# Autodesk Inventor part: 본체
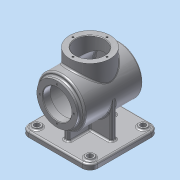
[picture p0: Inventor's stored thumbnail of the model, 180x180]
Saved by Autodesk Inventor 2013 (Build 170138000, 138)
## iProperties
Created: 2015-07
Part Number: 본체
Material: 알루미늄 6061
Document SubType Name: Modeling
Designer: Administrator
Density: 2.71 g/cm^3
Mass: 1277.74 g
Surface Area: 1267.61 cm^2
Volume: 471.49 cm^3
Author: Administrator
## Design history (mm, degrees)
sketch "스케치1"
  geometry: C1 r 45 at (0, 0); 1 further point
  constraints: 1 centre point, 1 coincident
  dimensions: "d0" = 90 diameter of C1
extrude "돌출1" new body sketch "스케치1" stored distance "d1" = 110; taper "d2" = 0 deg
sketch "스케치2"
  geometry: C1 r 45 at (0, 0) reference; C2 r 38 at (0, 0)
  constraints: 1 centre point, 1 coincident
  dimensions: "d3" = 76 diameter of C2
extrude "돌출2" join sketch "스케치2" distance "d4" = 7; taper "d5" = 0 deg
sketch "스케치3"
  geometry: C1 r 38 at (0, 0) reference; C2 r 27 at (0, 0)
  constraints: 1 centre point, 1 coincident
  dimensions: "d6" = 54 diameter of C2
extrude "돌출3" cut sketch "스케치3" distance "d7" = 14; taper "d8" = 0 deg
sketch "스케치4"
  geometry: C1 r 27 at (0, 0) reference; C2 r 40 at (0, 0)
  constraints: 1 centre point, 1 coincident
  dimensions: "d9" = 80 diameter of C2
extrude "돌출4" cut sketch "스케치4" distance "d10" = 96; taper "d11" = 0 deg
node "작업 평면1"
sketch "스케치5"
  geometry: L1 (-65, 65)-(65, 65); L2 (65, 65)-(65, -65); L3 (65, -65)-(-65, -65); L4 (-65, -65)-(-65, 65); L5 (-65, 65)-(65, -65); L6 (65, 65)-(-65, -65); 1 further point
  constraints: 12 end point, 2 midpoint, 2 parallel, 1 horizontal, 1 perpendicular
  dimensions: "d13" = 130 distance of L2.end L3.end; "d14" = 130 distance of L1.end L2.end
extrude "돌출5" join sketch "스케치5" distance "d15" = 10; taper "d16" = 0 deg
sketch "스케치6"
  geometry: L1 (-50, -50)-(50, -50); L2 (50, -50)-(50, 50); L3 (50, 50)-(-50, 50); L4 (-50, 50)-(-50, -50); L5 (-50, -50)-(50, 50); L6 (50, -50)-(-50, 50); C1 r 7.5 at (-50, 50); C2 r 7.5 at (50, 50); C3 r 7.5 at (50, -50); C4 r 7.5 at (-50, -50); 1 further point
  constraints: 12 end point, 4 centre point, 4 coincident, 2 midpoint, 2 parallel, 1 horizontal, 1 perpendicular
  dimensions: "d17" = 100 distance of L3.end L2.end; "d18" = 100 distance of L2.end L1.end; "d19" = 15 diameter of C1; "d20" = 15 diameter of C2; "d21" = 15 diameter of C3; "d22" = 15 diameter of C4
extrude "돌출6" join sketch "스케치6" distance "d23" = 3; taper "d24" = 0 deg
sketch "스케치7"
  geometry: C1 r 7.5 at (0, -100) reference; C2 r 7.5 at (-100, 0) reference; C3 r 7.5 at (0, 0) reference; C4 r 7.5 at (-100, -100) reference; C5 r 5 at (-100, 0); C6 r 5 at (0, 0); C7 r 5 at (0, -100); C8 r 5 at (-100, -100); 1 further point
  constraints: 4 centre point, 4 coincident
  dimensions: "d25" = 10 diameter of C5; "d26" = 10 diameter of C6; "d27" = 10 diameter of C7; "d28" = 10 diameter of C8
extrude "돌출7" cut sketch "스케치7" stored distance "d29" = 3; taper "d30" = 0 deg
node "작업 평면2"
sketch "스케치8"
  geometry: C1 r 38 at (0, 0); 1 further point
  constraints: 1 centre point, 1 coincident
  dimensions: "d32" = 76 diameter of C1
extrude "돌출8" join sketch "스케치8" stored distance "d33" = 3; taper "d34" = 0 deg
sketch "스케치9"
  geometry: C1 r 38 at (0, 0) reference; C2 r 27 at (0, 0)
  constraints: 1 centre point, 1 coincident
  dimensions: "d35" = 54 diameter of C2
extrude "돌출9" cut sketch "스케치9" stored distance "d36" = 3; taper "d37" = 0 deg
sketch "스케치10"
  geometry: C1 r 27 at (0, 0) reference; 1 further point
  constraints: 1 vertical alignment
  dimensions: "d38" = 32 distance of point (0, 32) C1.centre
hole "구멍1" sketch "스케치10" at (0, 32) diameter "d39" = 3.242; stored, may be unused: countersink angle "d43" = 90 deg, drill point angle "d45" = 118 deg; dims "d40" = 8, "d41" = 4, "d42" = 2, "d44" = 10
sketch "스케치11"
  geometry: C1 r 27 at (0, 0) reference; 1 further point
  constraints: 1 vertical alignment
  dimensions: "d49" = 32 distance of point (0, 32) C1.centre
hole "구멍2" sketch "스케치11" at (0, 32) diameter "d50" = 3.242; stored, may be unused: countersink angle "d54" = 90 deg, drill point angle "d56" = 118 deg; dims "d51" = 8, "d52" = 4, "d53" = 2, "d55" = 10
sketch "스케치12"
  geometry: L1 (-65, 65)-(-65, -65) reference; L2 (-5, 5)-(-5, 45); L3 (-5, 45)-(5, 45); L4 (5, 45)-(5, 5); L5 (5, 5)-(45, 5); L6 (45, 5)-(45, -5); L7 (45, -5)-(5, -5); L8 (5, -5)-(5, -45); L9 (5, -45)-(-5, -45); L10 (-5, -45)-(-5, -5); L11 (-5, -5)-(-45, -5); L12 (-45, -5)-(-45, 5); L13 (-45, 5)-(-5, 5); 5 further points
  constraints: 24 end point, 10 parallel, 5 equal length, 4 midpoint, 2 horizontal alignment, 2 vertical alignment, 1 collinear, 1 perpendicular
  dimensions: "d60" = 10 distance of L2.end L3.end; "d62" = 10 distance of L5.end L6.end; "d63" = 45 distance from line of L3 point (0, 0)
extrude "돌출10" join sketch "스케치12" stored distance "d64" = 3; taper "d65" = 0 deg
sketch "스케치13"
  geometry: C1 r 45 at (0, 0) reference; 1 further point
  constraints: 2 coincident, 1 other
feature "엠보싱1" sketch "스케치13" dims "d1" = 110, "d2" = 0, "d66" = 0.5, "d67" = 0
fillet "모깎기1" dims "d68" = 3
fillet "모깎기3" dims "d70" = 15
fillet "모깎기2" dims "d69" = 3
chamfer "모따기1" distance "d71" = 1; stored, may be unused: second distance "d72" = 2, angle "d73" = 45 deg
node "솔리드1"
pattern_circular "원형 패턴1" dims angle "d47" = 360 deg
pattern_circular "원형 패턴2" dims angle "d58" = 360 deg
node "절단 모서리 투영1"
other parameters: "d12" = -78
